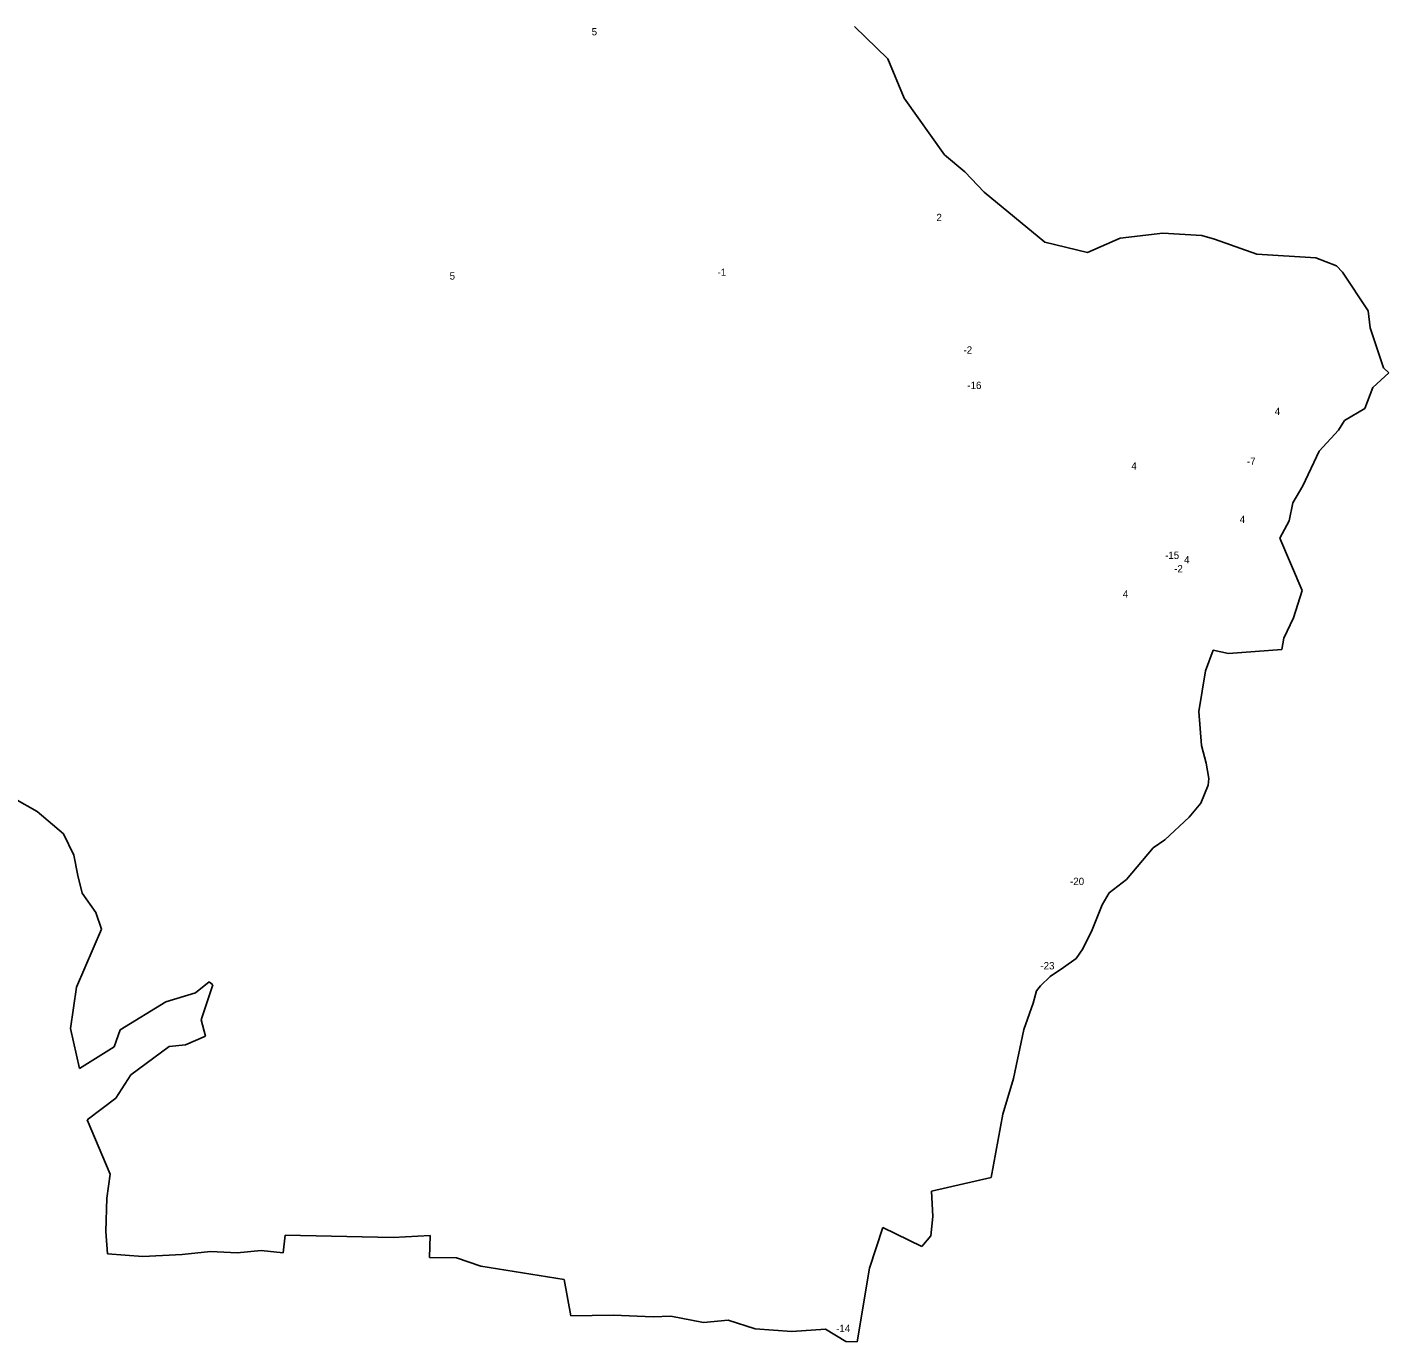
# Model space of a CAD drawing. Extents: x -791694 to -787831, y -969302 to -965696.
# Drawn here: x -789697 to -787831, y -969302 to -967500 of the extents above; entities that cross this region are included whole.
import ezdxf

# ---------------------------------------------------------------- set-up
doc = ezdxf.new("R2010")
doc.units = 0
doc.layers.add('Vrstva 13', color=7, linetype='Continuous')
doc.layers.add('Vrstva 15', color=7, linetype='Continuous')

msp = doc.modelspace()

# ---------------------------------------------------------------- linework, layer by layer
at = {"layer": 'Vrstva 13'}
for p, q in [((-788562.97, -967498.59), (-788517.3, -967542.94)), ((-788517.3, -967542.94), (-788494.96, -967596.97)), ((-788494.96, -967596.97), (-788439.62, -967674.68)), ((-788439.62, -967674.68), (-788411.95, -967698.02)), ((-788411.95, -967698.02), (-788385.3, -967725.71)), ((-788385.3, -967725.71), (-788302.29, -967794.41)), ((-788302.29, -967794.41), (-788243.62, -967808.42)), ((-788243.62, -967808.42), (-788198.95, -967789.07)), ((-788198.95, -967789.07), (-788140.28, -967782.07)), ((-788140.28, -967782.07), (-788086.95, -967785.41)), ((-788086.95, -967785.41), (-788069.62, -967790.08)), ((-788069.62, -967790.08), (-788011.61, -967811.09)), ((-788011.61, -967811.09), (-787930.94, -967815.75)), ((-787930.94, -967815.75), (-787902.27, -967827.09)), ((-787902.27, -967827.09), (-787894.28, -967835.43)), ((-787894.28, -967835.43), (-787859.28, -967888.78)), ((-787859.28, -967888.78), (-787856.28, -967911.79)), ((-787856.28, -967911.79), (-787837.94, -967966.82)), ((-787852.87, -967993.7), (-787830.84, -967973.57)), ((-787837.94, -967966.82), (-787830.84, -967973.57)), ((-787863.73, -968022.45), (-787852.87, -967993.7)), ((-787891.51, -968038.75), (-787863.73, -968022.45)), ((-787926.25, -968081.06), (-787899.9, -968052.3)), ((-787899.9, -968052.3), (-787891.51, -968038.75)), ((-787948.76, -968128.66), (-787926.25, -968081.06)), ((-787962.21, -968151.58), (-787948.76, -968128.66)), ((-787967.24, -968176.58), (-787962.21, -968151.58)), ((-787980.29, -968200.3), (-787967.24, -968176.58)), ((-787949.63, -968271.86), (-787980.29, -968200.3)), ((-787961.45, -968309.56), (-787949.63, -968271.86)), ((-787974.86, -968337.35), (-787961.45, -968309.56)), ((-788082.17, -968382.08), (-788071.63, -968353.96)), ((-788071.63, -968353.96), (-788050.55, -968358.43)), ((-788050.55, -968358.43), (-787977.42, -968352.68)), ((-787977.42, -968352.68), (-787974.86, -968337.35)), ((-788091.11, -968437.98), (-788082.17, -968382.08)), ((-788087.67, -968484.47), (-788091.11, -968437.98)), ((-788081.13, -968508.75), (-788087.67, -968484.47)), ((-788077.61, -968529.67), (-788081.13, -968508.75)), ((-788088.63, -968563.54), (-788078.25, -968538.94)), ((-788078.25, -968538.94), (-788077.61, -968529.67)), ((-789683.36, -968575.04), (-789714.03, -968557.7)), ((-789647.36, -968605.72), (-789683.36, -968575.04)), ((-788104.27, -968582.7), (-788088.63, -968563.54)), ((-788137.65, -968613.85), (-788104.27, -968582.7)), ((-789633.03, -968634.91), (-789647.36, -968605.72)), ((-788153.61, -968624.88), (-788137.65, -968613.85)), ((-789627.36, -968662.59), (-789633.03, -968634.91)), ((-788190.33, -968668.01), (-788153.61, -968624.88)), ((-789621.36, -968686.93), (-789627.36, -968662.59)), ((-788214.12, -968686.22), (-788190.33, -968668.01)), ((-789602.69, -968713.28), (-789621.36, -968686.93)), ((-788223.86, -968702.99), (-788214.12, -968686.22)), ((-788237.39, -968737.35), (-788223.86, -968702.99)), ((-789595.03, -968736.29), (-789602.69, -968713.28)), ((-789629.36, -968815.64), (-789595.03, -968736.29)), ((-788250.05, -968763.36), (-788237.39, -968737.35)), ((-788259.39, -968776.2), (-788250.05, -968763.36)), ((-788276.55, -968788.54), (-788259.39, -968776.2)), ((-788308.22, -968813.72), (-788294.89, -968801.05)), ((-788276.55, -968788.54), (-788294.89, -968801.05)), ((-789637.36, -968872.33), (-789629.36, -968815.64)), ((-789447.68, -968808.31), (-789466.02, -968823.65)), ((-789458.69, -968860.33), (-789442.35, -968812.31)), ((-789442.35, -968812.31), (-789447.68, -968808.31)), ((-788318.15, -968837.48), (-788313.72, -968820.55)), ((-788313.72, -968820.55), (-788308.22, -968813.72)), ((-789507.02, -968835.65), (-789569.69, -968874.33)), ((-789466.02, -968823.65), (-789507.02, -968835.65)), ((-788330.92, -968873.58), (-788318.15, -968837.48)), ((-789625.02, -968927.35), (-789637.36, -968872.33)), ((-789569.69, -968874.33), (-789577.69, -968897.34)), ((-789452.68, -968883), (-789458.69, -968860.33)), ((-788345.29, -968940.99), (-788330.92, -968873.58)), ((-789502.35, -968897.01), (-789480.02, -968894.67)), ((-789480.02, -968894.67), (-789452.68, -968883)), ((-789577.69, -968897.34), (-789625.02, -968927.35)), ((-789554.69, -968936.02), (-789502.35, -968897.01)), ((-789575.36, -968967.7), (-789554.69, -968936.02)), ((-788359.98, -968989.87), (-788345.29, -968940.99)), ((-789614.69, -968997.38), (-789575.36, -968967.7)), ((-789583.35, -969072.08), (-789614.69, -968997.38)), ((-788375.64, -969076.62), (-788359.98, -968989.87)), ((-789587.68, -969105.09), (-789583.35, -969072.08)), ((-788457.71, -969095.47), (-788375.64, -969076.62)), ((-788455.79, -969130.29), (-788457.71, -969095.47)), ((-789589.01, -969150.45), (-789587.68, -969105.09)), ((-788458.35, -969156.49), (-788455.79, -969130.29)), ((-789587.01, -969181.46), (-789589.01, -969150.45)), ((-789343.34, -969155.79), (-789346.01, -969179.8)), ((-789195.34, -969158.79), (-789343.34, -969155.79)), ((-789144.67, -969156.12), (-789195.34, -969158.79)), ((-789145.34, -969186.46), (-789144.67, -969156.12)), ((-788542.34, -969200.9), (-788524.45, -969145.31)), ((-788524.45, -969145.31), (-788470.8, -969171.18)), ((-788470.8, -969171.18), (-788458.35, -969156.49)), ((-789538.35, -969185.13), (-789587.01, -969181.46)), ((-789484.35, -969182.13), (-789538.35, -969185.13)), ((-789445.68, -969178.12), (-789484.35, -969182.13)), ((-789409.01, -969180.13), (-789445.68, -969178.12)), ((-789376.34, -969176.79), (-789409.01, -969180.13)), ((-789346.01, -969179.8), (-789376.34, -969176.79)), ((-789108.34, -969186.8), (-789145.34, -969186.46)), ((-789075.34, -969198.13), (-789108.34, -969186.8)), ((-788961, -969216.47), (-789075.34, -969198.13)), ((-788559.26, -969301.85), (-788542.34, -969200.9)), ((-788951.68, -969266.25), (-788961, -969216.47)), ((-788951.68, -969266.25), (-788893.39, -969265.28)), ((-788893.39, -969265.28), (-788838.78, -969267.52)), ((-788838.78, -969267.52), (-788814.83, -969266.56)), ((-788814.83, -969266.56), (-788769.81, -969275.51)), ((-788769.81, -969275.51), (-788736.27, -969272.31)), ((-788736.27, -969272.31), (-788699.23, -969284.13)), ((-788699.23, -969284.13), (-788649.09, -969287.65)), ((-788649.09, -969287.65), (-788602.78, -969284.45)), ((-788602.78, -969284.45), (-788575, -969301.38)), ((-788575, -969301.38), (-788559.26, -969301.85))]:
    msp.add_line(p, q, dxfattribs=at)

# ---------------------------------------------------------------- texts
at = {"layer": 'Vrstva 15'}
for s, p in [('5', (-788923.336, -967510.93)), ('2', (-788450.806, -967765.53)), ('-1', (-788750.764, -967840.55)), ('5', (-789118.006, -967845.74)), ('-2', (-788413.7, -967947.22)), ('-16', (-788408.438, -967995.69)), ('4', (-787987.182, -968031.48)), ('-7', (-788025.329, -968099.86)), ('4', (-788183.692, -968106.35)), ('4', (-788035.182, -968179.54)), ('-15', (-788137.414, -968228.7)), ('-2', (-788125.02, -968247.01)), ('4', (-788111.352, -968234.73)), ('4', (-788195.352, -968281.75)), ('-20', (-788267.69, -968675.72)), ('-23', (-788308.33, -968791.37)), ('-14', (-788588.26, -969288.55))]:
    msp.add_text(s, height=10, dxfattribs=at).set_placement(p)

doc.saveas('drawing.dxf')
